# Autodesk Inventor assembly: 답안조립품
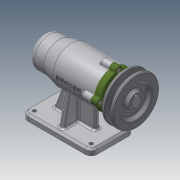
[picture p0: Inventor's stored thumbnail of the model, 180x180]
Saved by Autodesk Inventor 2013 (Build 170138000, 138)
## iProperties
Created: 2019-07
Part Number: 답안조립품
Document SubType Name: Assembly
Designer: 12
Author: 12
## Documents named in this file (12)
- C:\Users\12\Desktop\490704V1052\답안조립품.iam
- C:\Users\12\Desktop\490704V1052\본체.ipt
- C:\Users\12\Desktop\490704V1052\V벨트풀리.ipt
- C:\Users\12\Desktop\490704V1052\멈춤나사 M3.ipt
- C:\Users\12\Desktop\490704V1052\베어링 6004.ipt
- C:\Users\12\Desktop\490704V1052\베어링 51202.ipt
- C:\Users\12\Desktop\490704V1052\볼트 M4.ipt
- C:\Users\12\Desktop\490704V1052\어댑터슬리브.ipt
- C:\Users\12\Desktop\490704V1052\오일 실.ipt
- C:\Users\12\Desktop\490704V1052\축.ipt
- C:\Users\12\Desktop\490704V1052\커버.ipt
- C:\Users\12\Desktop\490704V1052\키 5 x 5 x 16.ipt
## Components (1 placed, 1 different names)
1. V벨트풀리:1
